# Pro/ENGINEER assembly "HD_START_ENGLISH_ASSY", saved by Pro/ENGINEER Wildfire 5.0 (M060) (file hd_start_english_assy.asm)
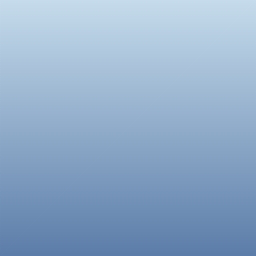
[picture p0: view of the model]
Units: Inch lbm Second (Pro/E Default); INCH, POUND, SECS

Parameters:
  DRW_UNITS = "ENGLISH"
  TOL_NAME = "INCHES"
  SUR = "250"

Other named items: ASIDE, ATOP, AFRONT, ACS_DEF, APT_ORIG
